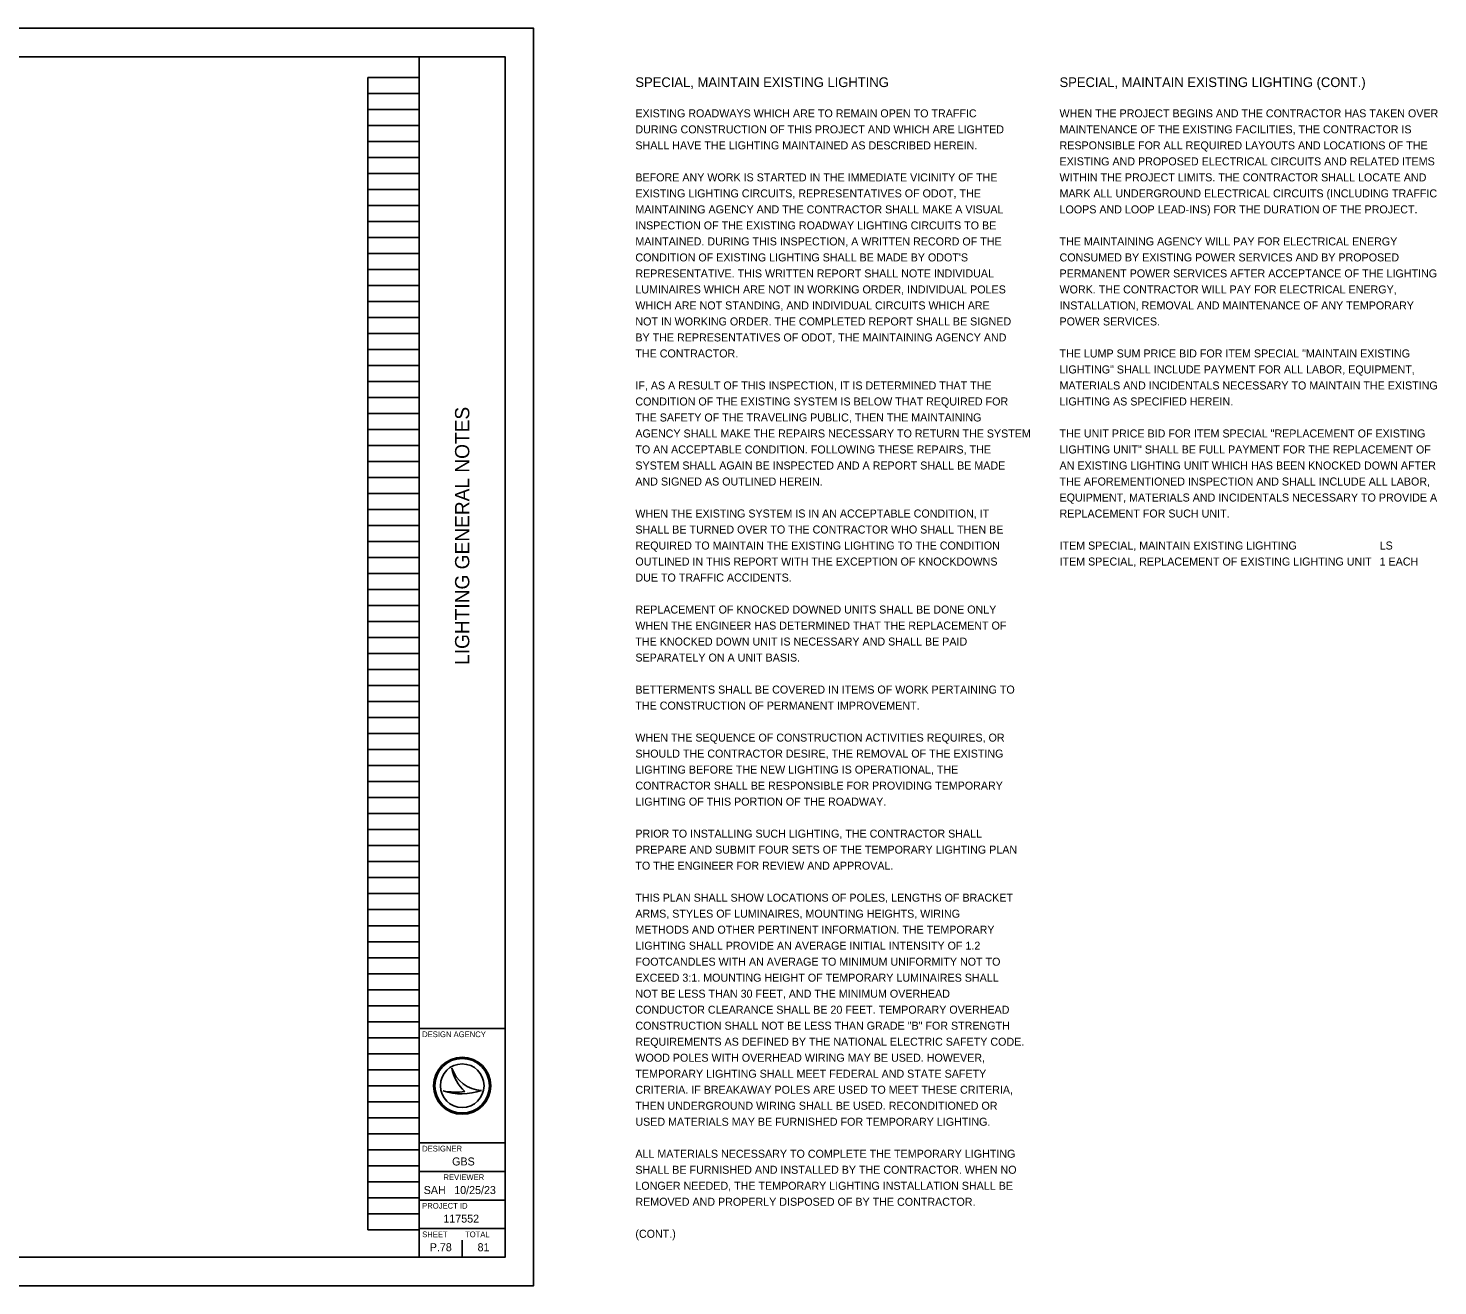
# Model space of a CAD drawing. Extents: x 0 to 49.8, y 0 to 22.
# Drawn here: x 25.16 to 49.82, y 0 to 22 of the extents above; entities that cross this region are included whole.
import ezdxf

# ---------------------------------------------------------------- set-up
doc = ezdxf.new("R2010")
doc.units = 0
for name, color, linetype in [('SH_Border', 7, 'Continuous'), ('SH_Cut_Line', 7, 'Continuous'), ('SH_Data', 7, 'Continuous'), ('SH_Text', 7, 'Continuous')]:
    doc.layers.add(name, color=color, linetype=linetype)

msp = doc.modelspace()

# ---------------------------------------------------------------- linework, layer by layer
at = {"layer": 'SH_Border'}
for p, q in [((32, 0.5), (32, 21.5)), ((32, 4.5), (33.5, 4.5)), ((32, 2.5), (33.5, 2.5)), ((32, 2), (33.5, 2)), ((32, 1.5), (33.5, 1.5)), ((32, 1), (33.5, 1))]:
    msp.add_line(p, q, dxfattribs=at)
msp.add_lwpolyline([(1.5, 21.5), (33.5, 21.5), (33.5, 0.5), (1.5, 0.5)], close=True, dxfattribs=at)
at = {"layer": 'SH_Cut_Line'}
msp.add_lwpolyline([(0, 0), (34, 0), (34, 22), (0, 22)], close=True, dxfattribs=at)
at = {"layer": 'SH_Data'}
for p, q in [((31.1, 0.98), (31.1, 21.14)), ((31.1, 21.14), (32, 21.14)), ((32, 0.98), (32, 21.14)), ((31.1, 20.86), (32, 20.86)), ((31.1, 20.58), (32, 20.58)), ((31.1, 20.3), (32, 20.3)), ((31.1, 20.02), (32, 20.02)), ((31.1, 19.74), (32, 19.74)), ((31.1, 19.46), (32, 19.46)), ((31.1, 19.18), (32, 19.18)), ((31.1, 18.9), (32, 18.9)), ((31.1, 18.62), (32, 18.62)), ((31.1, 18.34), (32, 18.34)), ((31.1, 18.06), (32, 18.06)), ((31.1, 17.78), (32, 17.78)), ((31.1, 17.5), (32, 17.5)), ((31.1, 17.22), (32, 17.22)), ((31.1, 16.94), (32, 16.94)), ((31.1, 16.66), (32, 16.66)), ((31.1, 16.38), (32, 16.38)), ((31.1, 16.1), (32, 16.1)), ((31.1, 15.82), (32, 15.82)), ((31.1, 15.54), (32, 15.54)), ((31.1, 15.26), (32, 15.26)), ((31.1, 14.98), (32, 14.98)), ((31.1, 14.7), (32, 14.7)), ((31.1, 14.42), (32, 14.42)), ((31.1, 14.14), (32, 14.14)), ((31.1, 13.86), (32, 13.86)), ((31.1, 13.58), (32, 13.58)), ((31.1, 13.3), (32, 13.3)), ((31.1, 13.02), (32, 13.02)), ((31.1, 12.74), (32, 12.74)), ((31.1, 12.46), (32, 12.46)), ((31.1, 12.18), (32, 12.18)), ((31.1, 11.9), (32, 11.9)), ((31.1, 11.62), (32, 11.62)), ((31.1, 11.34), (32, 11.34)), ((31.1, 11.06), (32, 11.06)), ((31.1, 10.78), (32, 10.78)), ((31.1, 10.5), (32, 10.5)), ((31.1, 10.22), (32, 10.22)), ((31.1, 9.94), (32, 9.94)), ((31.1, 9.66), (32, 9.66)), ((31.1, 9.38), (32, 9.38)), ((31.1, 9.1), (32, 9.1)), ((31.1, 8.82), (32, 8.82)), ((31.1, 8.54), (32, 8.54)), ((31.1, 8.26), (32, 8.26)), ((31.1, 7.98), (32, 7.98)), ((31.1, 7.7), (32, 7.7)), ((31.1, 7.42), (32, 7.42)), ((31.1, 7.14), (32, 7.14)), ((31.1, 6.86), (32, 6.86)), ((31.1, 6.58), (32, 6.58)), ((31.1, 6.3), (32, 6.3)), ((31.1, 6.02), (32, 6.02)), ((31.1, 5.74), (32, 5.74)), ((31.1, 5.46), (32, 5.46)), ((31.1, 5.18), (32, 5.18)), ((31.1, 4.9), (32, 4.9)), ((31.1, 4.62), (32, 4.62)), ((31.1, 4.34), (32, 4.34)), ((31.1, 4.06), (32, 4.06)), ((31.1, 3.78), (32, 3.78)), ((32.567, 3.81), (32.567, 3.81)), ((31.1, 3.5), (32, 3.5)), ((32.75, 3.5), (32.75, 3.5)), ((31.1, 3.22), (32, 3.22)), ((32.417, 3.41), (32.417, 3.41)), ((33.087, 3.419), (33.087, 3.419)), ((31.1, 2.94), (32, 2.94)), ((31.1, 2.66), (32, 2.66)), ((31.1, 2.38), (32, 2.38)), ((31.1, 2.1), (32, 2.1)), ((31.1, 1.82), (32, 1.82)), ((31.1, 1.54), (32, 1.54)), ((31.1, 1.26), (32, 1.26)), ((31.1, 0.98), (32, 0.98)), ((32.75, 0.5), (32.75, 0.8)), ((32.375, 0.675), (32.375, 0.675))]:
    msp.add_line(p, q, dxfattribs=at)
for radius in [0.5, 0.477, 0.477, 0.382]:
    msp.add_circle((32.75, 3.5), radius, dxfattribs=at)
for centre, radius, start, end in [((33.116, 3.998), 0.58, 198.9257, 198.9319), ((33.347, 3.97), 0.796, 191.6379, 191.6421), ((33.116, 3.998), 0.58, 198.9319, 267.1657), ((33.347, 3.97), 0.796, 191.6421, 226.0947), ((32.739, 4.37), 1.013, 251.4576, 290.0832), ((32.648, 4.654), 1.266, 259.4964, 259.4995), ((32.739, 4.37), 1.013, 251.4527, 251.4576), ((32.648, 4.654), 1.266, 259.4995, 276.6672)]:
    msp.add_arc(centre, radius, start, end, dxfattribs=at)

# ---------------------------------------------------------------- texts
msp.add_text('LIGHTING GENERAL NOTES', height=0.25, rotation=90, dxfattribs=at).set_placement((32.875, 10.862))
for s, height, p in [('DESIGN AGENCY', 0.1, (32.05, 4.35)), ('DESIGNER', 0.1, (32.05, 2.35)), ('GBS', 0.14, (32.574, 2.105)), ('SAH', 0.14, (32.077, 1.605)), ('REVIEWER', 0.1, (32.422, 1.85)), ('10/25/23', 0.14, (32.611, 1.605)), ('PROJECT ID', 0.1, (32.05, 1.35)), ('117552', 0.14, (32.421, 1.105)), ('SHEET', 0.1, (32.05, 0.85)), ('P.78', 0.14, (32.183, 0.605)), ('TOTAL', 0.1, (32.8, 0.85)), ('81', 0.14, (33.019, 0.605))]:
    msp.add_text(s, height=height, dxfattribs=at).set_placement(p)
at = {"layer": 'SH_Text'}
for s, height, p in [('SPECIAL, MAINTAIN EXISTING LIGHTING', 0.17, (35.78, 20.97)), ('SPECIAL, MAINTAIN EXISTING LIGHTING (CONT.)', 0.17, (43.2, 20.97)), ('EXISTING ROADWAYS WHICH ARE TO REMAIN OPEN TO TRAFFIC ', 0.14, (35.78, 20.44)), ('WHEN THE PROJECT BEGINS AND THE CONTRACTOR HAS TAKEN OVER ', 0.14, (43.2, 20.44)), ('DURING CONSTRUCTION OF THIS PROJECT AND WHICH ARE LIGHTED ', 0.14, (35.78, 20.16)), ('MAINTENANCE OF THE EXISTING FACILITIES, THE CONTRACTOR IS ', 0.14, (43.2, 20.16)), ('SHALL HAVE THE LIGHTING MAINTAINED AS DESCRIBED HEREIN.', 0.14, (35.78, 19.88)), ('RESPONSIBLE FOR ALL REQUIRED LAYOUTS AND LOCATIONS OF THE ', 0.14, (43.2, 19.88)), ('EXISTING AND PROPOSED ELECTRICAL CIRCUITS AND RELATED ITEMS ', 0.14, (43.2, 19.6)), ('BEFORE ANY WORK IS STARTED IN THE IMMEDIATE VICINITY OF THE ', 0.14, (35.78, 19.32)), ('WITHIN THE PROJECT LIMITS. THE CONTRACTOR SHALL LOCATE AND ', 0.14, (43.2, 19.32)), ('EXISTING LIGHTING CIRCUITS, REPRESENTATIVES OF ODOT, THE ', 0.14, (35.78, 19.04)), ('MARK ALL UNDERGROUND ELECTRICAL CIRCUITS (INCLUDING TRAFFIC ', 0.14, (43.2, 19.04)), ('MAINTAINING AGENCY AND THE CONTRACTOR SHALL MAKE A VISUAL ', 0.14, (35.78, 18.76)), ('LOOPS AND LOOP LEAD-INS) FOR THE DURATION OF THE PROJECT.', 0.14, (43.2, 18.76)), ('INSPECTION OF THE EXISTING ROADWAY LIGHTING CIRCUITS TO BE ', 0.14, (35.78, 18.48)), ('MAINTAINED. DURING THIS INSPECTION, A WRITTEN RECORD OF THE ', 0.14, (35.78, 18.2)), ('THE MAINTAINING AGENCY WILL PAY FOR ELECTRICAL ENERGY ', 0.14, (43.2, 18.2)), ("CONDITION OF EXISTING LIGHTING SHALL BE MADE BY ODOT'S ", 0.14, (35.78, 17.92)), ('CONSUMED BY EXISTING POWER SERVICES AND BY PROPOSED ', 0.14, (43.2, 17.92)), ('REPRESENTATIVE. THIS WRITTEN REPORT SHALL NOTE INDIVIDUAL ', 0.14, (35.78, 17.64)), ('PERMANENT POWER SERVICES AFTER ACCEPTANCE OF THE LIGHTING ', 0.14, (43.2, 17.64)), ('LUMINAIRES WHICH ARE NOT IN WORKING ORDER, INDIVIDUAL POLES ', 0.14, (35.78, 17.36)), ('WORK. THE CONTRACTOR WILL PAY FOR ELECTRICAL ENERGY, ', 0.14, (43.2, 17.36)), ('WHICH ARE NOT STANDING, AND INDIVIDUAL CIRCUITS WHICH ARE ', 0.14, (35.78, 17.08)), ('INSTALLATION, REMOVAL AND MAINTENANCE OF ANY TEMPORARY ', 0.14, (43.2, 17.08)), ('NOT IN WORKING ORDER. THE COMPLETED REPORT SHALL BE SIGNED', 0.14, (35.78, 16.8)), ('POWER SERVICES.', 0.14, (43.2, 16.8)), ('BY THE REPRESENTATIVES OF ODOT, THE MAINTAINING AGENCY AND ', 0.14, (35.78, 16.52)), ('THE CONTRACTOR.', 0.14, (35.78, 16.24)), ('THE LUMP SUM PRICE BID FOR ITEM SPECIAL "MAINTAIN EXISTING ', 0.14, (43.2, 16.24)), ('LIGHTING" SHALL INCLUDE PAYMENT FOR ALL LABOR, EQUIPMENT, ', 0.14, (43.2, 15.96)), ('IF, AS A RESULT OF THIS INSPECTION, IT IS DETERMINED THAT THE ', 0.14, (35.78, 15.68)), ('MATERIALS AND INCIDENTALS NECESSARY TO MAINTAIN THE EXISTING ', 0.14, (43.2, 15.68)), ('CONDITION OF THE EXISTING SYSTEM IS BELOW THAT REQUIRED FOR ', 0.14, (35.78, 15.4)), ('LIGHTING AS SPECIFIED HEREIN.', 0.14, (43.2, 15.4)), ('THE SAFETY OF THE TRAVELING PUBLIC, THEN THE MAINTAINING ', 0.14, (35.78, 15.12)), ('AGENCY SHALL MAKE THE REPAIRS NECESSARY TO RETURN THE SYSTEM ', 0.14, (35.78, 14.84)), ('THE UNIT PRICE BID FOR ITEM SPECIAL "REPLACEMENT OF EXISTING ', 0.14, (43.2, 14.84)), ('TO AN ACCEPTABLE CONDITION. FOLLOWING THESE REPAIRS, THE ', 0.14, (35.78, 14.56)), ('LIGHTING UNIT" SHALL BE FULL PAYMENT FOR THE REPLACEMENT OF ', 0.14, (43.2, 14.56)), ('SYSTEM SHALL AGAIN BE INSPECTED AND A REPORT SHALL BE MADE ', 0.14, (35.78, 14.28)), ('AN EXISTING LIGHTING UNIT WHICH HAS BEEN KNOCKED DOWN AFTER ', 0.14, (43.2, 14.28)), ('AND SIGNED AS OUTLINED HEREIN.', 0.14, (35.78, 14)), ('THE AFOREMENTIONED INSPECTION AND SHALL INCLUDE ALL LABOR, ', 0.14, (43.2, 14)), ('EQUIPMENT, MATERIALS AND INCIDENTALS NECESSARY TO PROVIDE A ', 0.14, (43.2, 13.72)), ('WHEN THE EXISTING SYSTEM IS IN AN ACCEPTABLE CONDITION, IT ', 0.14, (35.78, 13.44)), ('REPLACEMENT FOR SUCH UNIT.', 0.14, (43.2, 13.44)), ('SHALL BE TURNED OVER TO THE CONTRACTOR WHO SHALL THEN BE ', 0.14, (35.78, 13.16)), ('REQUIRED TO MAINTAIN THE EXISTING LIGHTING TO THE CONDITION  ', 0.14, (35.78, 12.88)), ('ITEM SPECIAL, MAINTAIN EXISTING LIGHTING', 0.14, (43.2, 12.88)), ('LS', 0.14, (48.8, 12.88)), ('OUTLINED IN THIS REPORT WITH THE EXCEPTION OF KNOCKDOWNS ', 0.14, (35.78, 12.6)), ('ITEM SPECIAL, REPLACEMENT OF EXISTING LIGHTING UNIT', 0.14, (43.2, 12.6)), ('1 EACH ', 0.14, (48.8, 12.6)), ('DUE TO TRAFFIC ACCIDENTS.', 0.14, (35.78, 12.32)), ('REPLACEMENT OF KNOCKED DOWNED UNITS SHALL BE DONE ONLY ', 0.14, (35.78, 11.76)), ('WHEN THE ENGINEER HAS DETERMINED THAT THE REPLACEMENT OF ', 0.14, (35.78, 11.48)), ('THE KNOCKED DOWN UNIT IS NECESSARY AND SHALL BE PAID ', 0.14, (35.78, 11.2)), ('SEPARATELY ON A UNIT BASIS.', 0.14, (35.78, 10.92)), ('BETTERMENTS SHALL BE COVERED IN ITEMS OF WORK PERTAINING TO ', 0.14, (35.78, 10.36)), ('THE CONSTRUCTION OF PERMANENT IMPROVEMENT.', 0.14, (35.78, 10.08)), ('WHEN THE SEQUENCE OF CONSTRUCTION ACTIVITIES REQUIRES, OR ', 0.14, (35.78, 9.52)), ('SHOULD THE CONTRACTOR DESIRE, THE REMOVAL OF THE EXISTING ', 0.14, (35.78, 9.24)), ('LIGHTING BEFORE THE NEW LIGHTING IS OPERATIONAL, THE ', 0.14, (35.78, 8.96)), ('CONTRACTOR SHALL BE RESPONSIBLE FOR PROVIDING TEMPORARY ', 0.14, (35.78, 8.68)), ('LIGHTING OF THIS PORTION OF THE ROADWAY.', 0.14, (35.78, 8.4)), ('PRIOR TO INSTALLING SUCH LIGHTING, THE CONTRACTOR SHALL ', 0.14, (35.78, 7.84)), ('PREPARE AND SUBMIT FOUR SETS OF THE TEMPORARY LIGHTING PLAN ', 0.14, (35.78, 7.56)), ('TO THE ENGINEER FOR REVIEW AND APPROVAL.', 0.14, (35.78, 7.28)), ('THIS PLAN SHALL SHOW LOCATIONS OF POLES, LENGTHS OF BRACKET ', 0.14, (35.78, 6.72)), ('ARMS, STYLES OF LUMINAIRES, MOUNTING HEIGHTS, WIRING ', 0.14, (35.78, 6.44)), ('METHODS AND OTHER PERTINENT INFORMATION. THE TEMPORARY ', 0.14, (35.78, 6.16)), ('LIGHTING SHALL PROVIDE AN AVERAGE INITIAL INTENSITY OF 1.2 ', 0.14, (35.78, 5.88)), ('FOOTCANDLES WITH AN AVERAGE TO MINIMUM UNIFORMITY NOT TO ', 0.14, (35.78, 5.6)), ('EXCEED 3:1. MOUNTING HEIGHT OF TEMPORARY LUMINAIRES SHALL ', 0.14, (35.78, 5.32)), ('NOT BE LESS THAN 30 FEET, AND THE MINIMUM OVERHEAD ', 0.14, (35.78, 5.04)), ('CONDUCTOR CLEARANCE SHALL BE 20 FEET. TEMPORARY OVERHEAD ', 0.14, (35.78, 4.76)), ('CONSTRUCTION SHALL NOT BE LESS THAN GRADE "B" FOR STRENGTH ', 0.14, (35.78, 4.48)), ('REQUIREMENTS AS DEFINED BY THE NATIONAL ELECTRIC SAFETY CODE. ', 0.14, (35.78, 4.2)), ('WOOD POLES WITH OVERHEAD WIRING MAY BE USED. HOWEVER, ', 0.14, (35.78, 3.92)), ('TEMPORARY LIGHTING SHALL MEET FEDERAL AND STATE SAFETY ', 0.14, (35.78, 3.64)), ('CRITERIA. IF BREAKAWAY POLES ARE USED TO MEET THESE CRITERIA, ', 0.14, (35.78, 3.36)), ('THEN UNDERGROUND WIRING SHALL BE USED. RECONDITIONED OR ', 0.14, (35.78, 3.08)), ('USED MATERIALS MAY BE FURNISHED FOR TEMPORARY LIGHTING.', 0.14, (35.78, 2.8)), ('ALL MATERIALS NECESSARY TO COMPLETE THE TEMPORARY LIGHTING ', 0.14, (35.78, 2.24)), ('SHALL BE FURNISHED AND INSTALLED BY THE CONTRACTOR. WHEN NO ', 0.14, (35.78, 1.96)), ('LONGER NEEDED, THE TEMPORARY LIGHTING INSTALLATION SHALL BE ', 0.14, (35.78, 1.68)), ('REMOVED AND PROPERLY DISPOSED OF BY THE CONTRACTOR.', 0.14, (35.78, 1.4)), ('(CONT.)', 0.14, (35.78, 0.84))]:
    msp.add_text(s, height=height, dxfattribs=at).set_placement(p)

doc.saveas('drawing.dxf')
